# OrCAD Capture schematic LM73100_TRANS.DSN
size E; title: LM73100: 2.7- 23 V, 5.5 A Integrated Ideal Diode with Input; rev: 1.0; note: Datasheet: SNOSDC0     EVM: SNOU173; note: Reverse Polarity and Overvoltage Protection
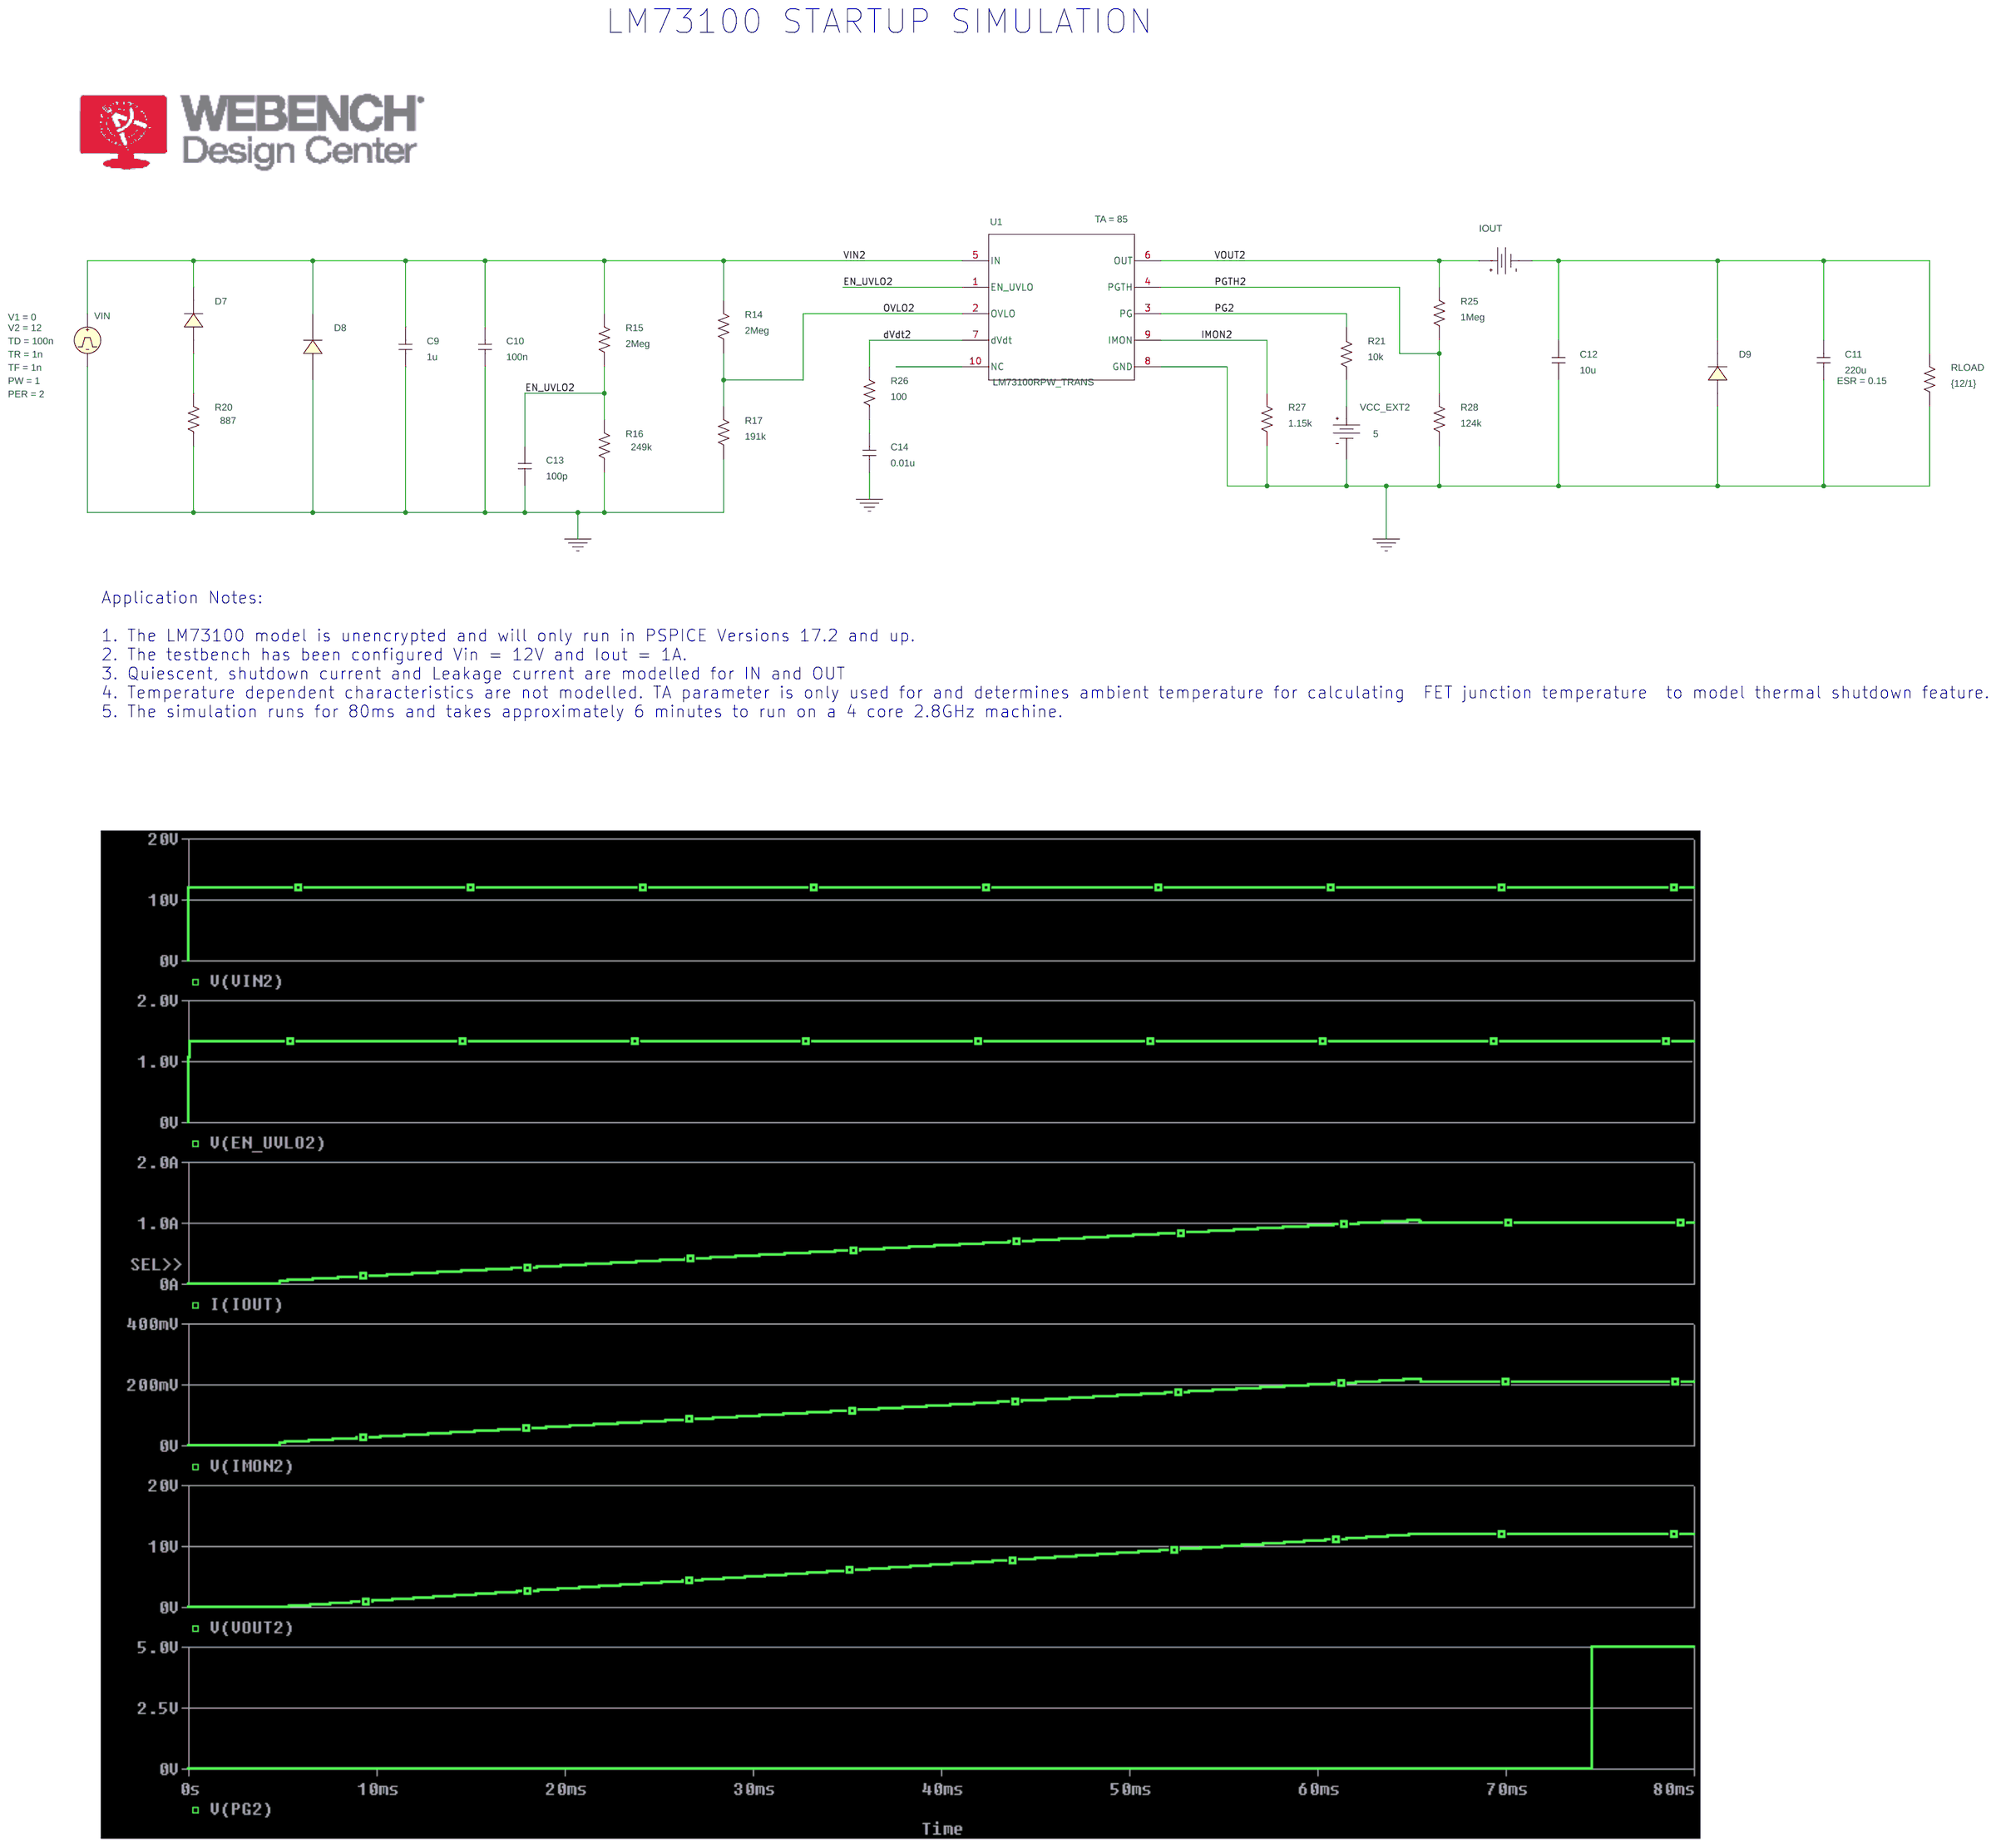
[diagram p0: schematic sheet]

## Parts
C9  1u  [RAD/CK05]
C10  100n  [RAD/CK05]
C11  220u  [RAD/CK05]
C12  10u  [RAD/CK05]
C13  100p  [RAD/CK05]
C14  0.01u  [RAD/CK05]
D7  DI_DDZ30D
D8  SMBJ18A
D9  B330A
IOUT  VDC
R14  2Meg  [AX/RC05]
R15  2Meg  [AX/RC05]
R16  249k  [AX/RC05]
R17  191k  [AX/RC05]
R20  887  [AX/RC05]
R21  10k  [AX/RC05]
R25  1Meg  [AX/RC05]
R26  100  [AX/RC05]
R27  1.15k  [AX/RC05]
R28  124k  [AX/RC05]
RLOAD  {12/1}  [AX/RC05]
U1  LM73100RPW_TRANS  [RPW0010A-MFG]
VCC_EXT2  VDC
VIN  VPULSE

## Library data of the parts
C9 C10 C13 C14 = C
C11 = C: AppProp: InductiveSlave:;SRF:;PrevCap:1u;PrevESL:; ESR: 0.15
C12 = C: AppProp: InductiveSlave:;SRF:;PrevCap:220u;PrevESL:; ESR: 0.15
D7 D8 = D_D1: PSpiceTemplate: X^@REFDES  %C %A @MODEL
D9 = D_D1: PSpiceTemplate: D^@REFDES  %A %C @MODEL ?AREA/@AREA/
IOUT = VDC
R14-R17 R20 R21 R25-R28 RLOAD = R
U1 = LM73100RPW_TRANS: TA: 85
VCC_EXT2 = VDC: DC: 5
VIN = VPULSE: PER: 2; PW: 1; TD: 100n; TF: 1n; TR: 1n; V1: 0; V2: 12

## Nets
VIN2: C9.2 C10.2 D7.1(C) D8.1(C) R14.2 R15.2 U1.5(IN) VIN.1(+)
0: C9.1 C10.1 C11.1 C12.1 C13.1 C14.1 D8.2(A) D9.2(A) R16.1 R17.1 R20.1 R27.1 R28.1 RLOAD.1 U1.8(GND) VCC_EXT2.1(-) VIN.2(-)
dVdt2: R26.2 U1.7(dVdt)
EN_UVLO2: C13.2 R15.1 R16.2 U1.1(EN_UVLO)
IMON2: R27.2 U1.9(IMON)
OVLO2: R14.1 R17.2 U1.2(OVLO)
PG2: R21.1 U1.3(PG)
PGTH2: R25.1 R28.2 U1.4(PGTH)
VOUT2: IOUT.0(+) R25.2 U1.6(OUT)
N55534: C11.2 C12.2 D9.1(C) IOUT.1(-) RLOAD.2
N59784: R21.2 VCC_EXT2.0(+)
N61002: D7.2(A) R20.2
N62462: C14.2 R26.1

Not connected (* = marked no-connect by the designer): U1 10(NC)

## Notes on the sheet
- LM73100 STARTUP SIMULATION
- Application Notes:
  1. The LM73100 model is unencrypted and will only run in PSPICE Versions 17.2 and up.
  2. The testbench has been configured Vin = 12V and Iout = 1A.
  3. Quiescent, shutdown current and Leakage current are modelled for IN and OUT
  4. Temperature dependent characteristics are not modelled. TA parameter is only used for and determines ambient temperature for calculating  FET junction temperature  to model thermal shutdown feature.
  5. The simulation runs for 80ms and takes approximately 6 minutes to run on a 4 core 2.8GHz machine.
